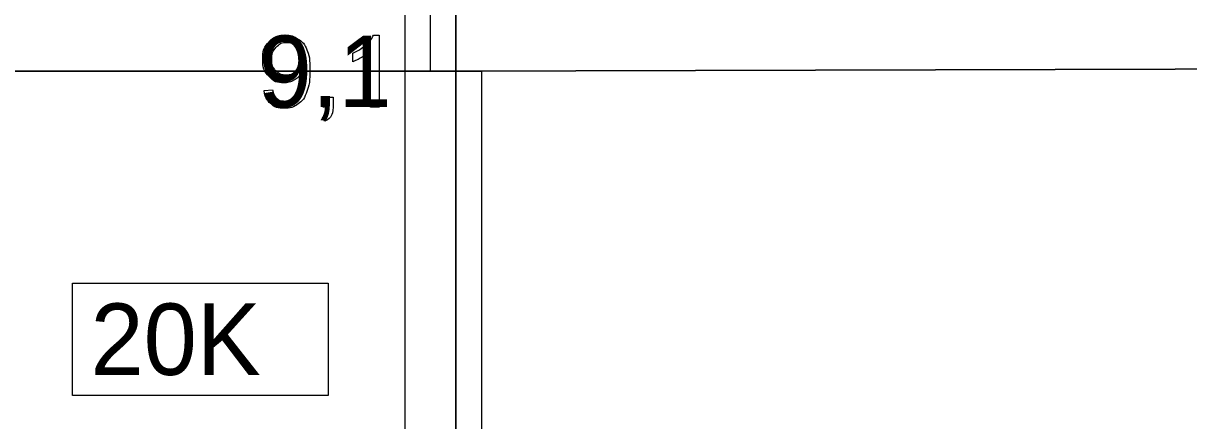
# Model space of a CAD drawing. Extents: x 532503 to 539665, y 6557663 to 6561526.
# Drawn here: x 537646.5 to 537737.8, y 6560299.7 to 6560330.8 of the extents above; entities that cross this region are included whole.
import ezdxf

# ---------------------------------------------------------------- set-up
doc = ezdxf.new("R2010")
doc.units = 0
for name, color, linetype in [('Default', 7, 'Continuous'), ('GEOLPUNKT', 7, 'Continuous'), ('Proovid', 7, 'Continuous'), ('Täide', 7, 'Continuous')]:
    doc.layers.add(name, color=color, linetype=linetype)

msp = doc.modelspace()

# ---------------------------------------------------------------- linework, layer by layer
at = {"layer": 'Default'}
msp.add_lwpolyline([(537557.214, 6560327.079), (537680.404, 6560327.07), (537793.03, 6560327.388)], dxfattribs=at)
at = {"layer": 'GEOLPUNKT'}
msp.add_line((537680.404, 6560509.07), (537680.404, 6560181.07), dxfattribs=at)
at = {"layer": 'Proovid'}
for points in [[(537680.404, 6560399.07), (537676.404, 6560399.07), (537676.404, 6560289.07), (537680.404, 6560289.07)], [(537680.404, 6560375.07), (537678.404, 6560375.07), (537678.404, 6560327.07), (537680.404, 6560327.07)], [(537680.404, 6560327.07), (537682.404, 6560327.07), (537682.404, 6560285.07), (537680.404, 6560285.07)], [(537650.404, 6560310.47), (537670.404, 6560310.47), (537670.404, 6560301.67), (537650.404, 6560301.67)]]:
    msp.add_lwpolyline(points, close=True, dxfattribs=at)
for points in [[(537673.961, 6560329.892), (537674.404, 6560329.892), (537674.404, 6560324.27)], [(537672.343, 6560327.822), (537672.343, 6560328.486)], [(537674.404, 6560324.27), (537673.717, 6560324.27), (537673.717, 6560328.65)], [(537665.398, 6560325.568), (537666.06, 6560325.628)], [(537670.016, 6560324.27), (537670.016, 6560325.051), (537670.798, 6560325.051), (537670.798, 6560324.27)], [(537670.405, 6560324.27), (537670.016, 6560324.27)], [(537670.162, 6560323.16), (537669.969, 6560323.455)]]:
    msp.add_lwpolyline(points, dxfattribs=at)
for points in [[(537666.06, 6560325.628), (537666.144, 6560325.161), (537666.38, 6560324.95), (537666.617, 6560324.74), (537666.987, 6560324.74), (537667.303, 6560324.74), (537667.543, 6560324.885), (537667.783, 6560325.03), (537667.934, 6560325.273), (537668.086, 6560325.516), (537668.189, 6560325.929), (537668.292, 6560326.341), (537668.292, 6560326.769), (537668.292, 6560326.815), (537668.288, 6560326.907), (537668.082, 6560326.578), (537667.725, 6560326.374), (537667.368, 6560326.17), (537666.952, 6560326.17), (537666.257, 6560326.17), (537665.777, 6560326.674), (537665.296, 6560327.177), (537665.296, 6560328.002), (537665.296, 6560328.853), (537665.798, 6560329.372), (537666.299, 6560329.892), (537667.055, 6560329.892), (537667.601, 6560329.892), (537668.053, 6560329.598), (537668.506, 6560329.304), (537668.74, 6560328.76), (537668.975, 6560328.216), (537668.975, 6560327.185), (537668.975, 6560326.112), (537668.742, 6560325.476), (537668.509, 6560324.841), (537668.049, 6560324.508), (537667.589, 6560324.176), (537666.971, 6560324.176), (537666.314, 6560324.176), (537665.898, 6560324.541), (537665.482, 6560324.906), (537665.398, 6560325.568)], [(537668.211, 6560328.036), (537668.211, 6560328.629), (537667.898, 6560328.976), (537667.584, 6560329.324), (537667.14, 6560329.324), (537666.68, 6560329.324), (537666.342, 6560328.949), (537666.004, 6560328.575), (537666.004, 6560327.979), (537666.004, 6560327.444), (537666.325, 6560327.11), (537666.646, 6560326.776), (537667.121, 6560326.776), (537667.597, 6560326.776), (537667.904, 6560327.11), (537668.211, 6560327.444), (537668.211, 6560328.036)], [(537672.343, 6560328.486), (537672.919, 6560328.757), (537673.351, 6560329.143), (537673.782, 6560329.529), (537673.961, 6560329.892)], [(537673.717, 6560328.65), (537673.469, 6560328.414), (537673.066, 6560328.177), (537672.663, 6560327.94), (537672.343, 6560327.822)], [(537669.969, 6560323.455), (537670.187, 6560323.551), (537670.29, 6560323.736), (537670.394, 6560323.922), (537670.405, 6560324.27)], [(537670.798, 6560324.27), (537670.798, 6560323.838), (537670.645, 6560323.572), (537670.493, 6560323.306), (537670.162, 6560323.16)]]:
    msp.add_open_spline(points, degree=3, dxfattribs=at)
at = {"layer": 'Täide'}
for p, q in [((537793.03, 6560327.388), (537680.404, 6560327.07)), ((537680.404, 6560327.07), (537557.214, 6560327.079))]:
    msp.add_line(p, q, dxfattribs=at)
for points in [[(537557.214, 6560327.079), (537680.404, 6560327.07), (537793.03, 6560327.388)], [(537793.03, 6560327.388), (537680.404, 6560327.07), (537557.214, 6560327.079)]]:
    msp.add_lwpolyline(points, dxfattribs=at)

# ---------------------------------------------------------------- texts
at = {"layer": 'Proovid'}
for s, p in [('9,1', (537664.971, 6560324.27)), ('20K', (537651.804, 6560303.27))]:
    msp.add_text(s, height=5.6, dxfattribs=at).set_placement(p)

doc.saveas('drawing.dxf')
